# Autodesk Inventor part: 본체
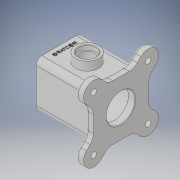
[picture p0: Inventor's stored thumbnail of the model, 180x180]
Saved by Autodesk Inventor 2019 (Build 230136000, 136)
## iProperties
Created: 2021-01
Part Number: 본체
Material: 일반
Document SubType Name: Modeling
Designer: 3dpro21
Density: 1 g/cm^3
Appearance: 기본값
Author: 3dpro21
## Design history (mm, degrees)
sketch "스케치1"
  geometry: L1 (-40, 40)-(40, 40); L2 (40, 40)-(40, -40); L3 (40, -40)-(-40, -40); L4 (-40, -40)-(-40, 40); 3 further points
  constraints: 8 end point, 2 midpoint, 2 parallel, 1 horizontal, 1 horizontal alignment, 1 perpendicular, 1 vertical alignment
  dimensions: "d0" = 80 distance of L2.end L3.end; "d1" = 80 distance of L1.end L2.end
extrude "돌출1" new body sketch "스케치1" stored distance "d2" = 108; taper "d3" = 0 deg
sketch "스케치2"
  geometry: C1 r 35 at (0, 0); 1 further point
  constraints: 1 centre point, 1 coincident
  dimensions: "d4" = 70 diameter of C1
extrude "돌출2" cut sketch "스케치2" stored distance "d5" = 84; taper "d6" = 0 deg
sketch "스케치3"
  geometry: C1 r 25 at (0, 0); 1 further point
  constraints: 1 centre point, 1 coincident
  dimensions: "d7" = 50 diameter of C1
extrude "돌출3" cut sketch "스케치3" distance "d8" = 108; taper "d9" = 0 deg
sketch "스케치4"
  geometry: L1 (-48, -48)-(48, -48); L2 (48, -48)-(48, 48); L3 (48, 48)-(-48, 48); L4 (-48, 48)-(-48, -48); L5 (-48, -48)-(48, 48); L6 (48, -48)-(-48, 48); C1 r 25 at (0, 0) reference; 1 further point
  constraints: 12 end point, 2 midpoint, 2 parallel, 1 horizontal, 1 perpendicular
  dimensions: "d10" = 96 distance of L3.end L2.end; "d11" = 96 distance of L2.end L1.end
extrude "돌출4" join sketch "스케치4" distance "d12" = 12; taper "d13" = 0 deg
sketch "스케치5" dims "d50" = 134
  geometry: L1 (0, 0)-(0, 48); L2 (-48, 48)-(48, 48) reference; L3 (0, 0)-(47.376, 47.376); L4 (48, -48)-(48, 48) reference; L5 (34.648, 60.104)-(22.544, 48); L6 (60.104, 34.648)-(48, 22.544); L7 (48, 48)-(-48, 48) reference; L8 (22.544, 48)-(48, 22.544); A1 r 18 centre (47.376, 47.376) between (34.648, 60.104) and (60.104, 34.648); 1 further point
  constraints: 10 end point, 2 point on circle, 2 point on line, 2 tangent, 1 centre point, 1 coincident, 1 midpoint, 1 parallel, 3 other
  dimensions: "d14" = 36 diameter of A1; "d51" = 45 deg angle of L3 L1; "d59" = 45 deg angle of L1 L5
extrude "돌출5" join sketch "스케치5" distance "d15" = 12; taper "d16" = 0 deg
sketch "스케치8"
  geometry: L1 (96, 105.376)-(96, 100.104) reference; L2 (108, 62.544)-(108, -8) reference; C1 r 20 at (49, 40); 7 further points
  constraints: 1 centre point, 1 horizontal alignment, 1 point on line
  dimensions: "d27" = 40 diameter of C1; "d28" = 47 distance from line of L1 C1.centre
extrude "돌출6" join sketch "스케치8" distance "d29" = 15; taper "d30" = 0 deg
sketch "스케치9"
  geometry: C1 r 20 at (0, 0) reference; 2 further points
  constraints: 1 coincident
hole "구멍2" sketch "스케치9" at (0, 0) diameter "d31" = 25; stored, may be unused: countersink angle "d35" = 90 deg, drill point angle "d37" = 0 deg; dims "d32" = 8, "d33" = 30, "d34" = 8, "d36" = 11.8
fillet "모깎기2" dims "d39" = 10
chamfer "모따기1" distance "d41" = 1; stored, may be unused: second distance "d42" = 2, angle "d43" = 45 deg
chamfer "모따기2" distance "d44" = 1; stored, may be unused: second distance "d45" = 2, angle "d46" = 45 deg
chamfer "모따기3" distance "d47" = 1; stored, may be unused: second distance "d48" = 2, angle "d49" = 45 deg
sketch "스케치12"
  geometry: A1 r 18 centre (-47.376, 47.376) between (-34.648, 60.104) and (-60.104, 34.648) reference; 2 further points
  constraints: 1 coincident
hole "구멍5" sketch "스케치12" at (-47.376, 47.376) diameter "d71" = 10; stored, may be unused: countersink angle "d75" = 90 deg, drill point angle "d77" = 118 deg; dims "d72" = 8, "d73" = 18, "d74" = 4, "d76" = 10
fillet "모깎기4" dims "d81" = 20
fillet "모깎기5" dims "d82" = 3
fillet "모깎기6" dims "d83" = 3
sketch "스케치13"
  geometry: 2 further points
  dimensions: "d84" = 30 horizontal distance of point (0, 0) point (30, 30); "d85" = 30 horizontal distance of point (0, 0) point (30, 30)
hole "구멍6" sketch "스케치13" at (30, 30) diameter "d86" = 3.242; stored, may be unused: countersink angle "d90" = 90 deg, drill point angle "d92" = 118 deg; dims "d87" = 8, "d88" = 18, "d89" = 4, "d91" = 10
sketch "스케치14"
  geometry: L1 (0, 0)-(0, 60) reference; L2 (93, 65)-(93, -5) reference; L3 (15, -5)-(15, 65) reference; C1 r 20 at (49, 30) reference; 3 further points
  constraints: 1 horizontal alignment, 2 other
  dimensions: "d96" = 10 distance from line of L1 point (10, 30)
feature "엠보싱1" sketch "스케치14" dims "d0" = 80, "d1" = 80, "d10" = 96, "d11" = 96, "d97" = 0.5, "d98" = 0
node "솔리드1"
pattern_circular "원형 패턴3" dims angle "d79" = 360 deg
pattern_circular "원형 패턴4" dims angle "d94" = 360 deg
node "투영된 루프2"
